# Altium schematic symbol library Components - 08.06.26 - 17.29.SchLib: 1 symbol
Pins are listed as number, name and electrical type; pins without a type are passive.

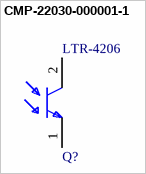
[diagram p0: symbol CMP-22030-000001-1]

## CMP-22030-000001-1
designator Q?, comment LTR-4206
SENSOR PHOTO 940NM TOP VIEW T1; Manufacturer: Lite-On; Viewing Angle: 20°; Wavelength: 900nm; Fall Time: 10us; Dark Current: 0.1uA; Collector Emitter Breakdown Voltage: 30V; Power Dissipation: 100mW; Max Collector Current: 9.6mA
footprint FP-LTR-4206-MFG
pins: 1 E, 2 C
